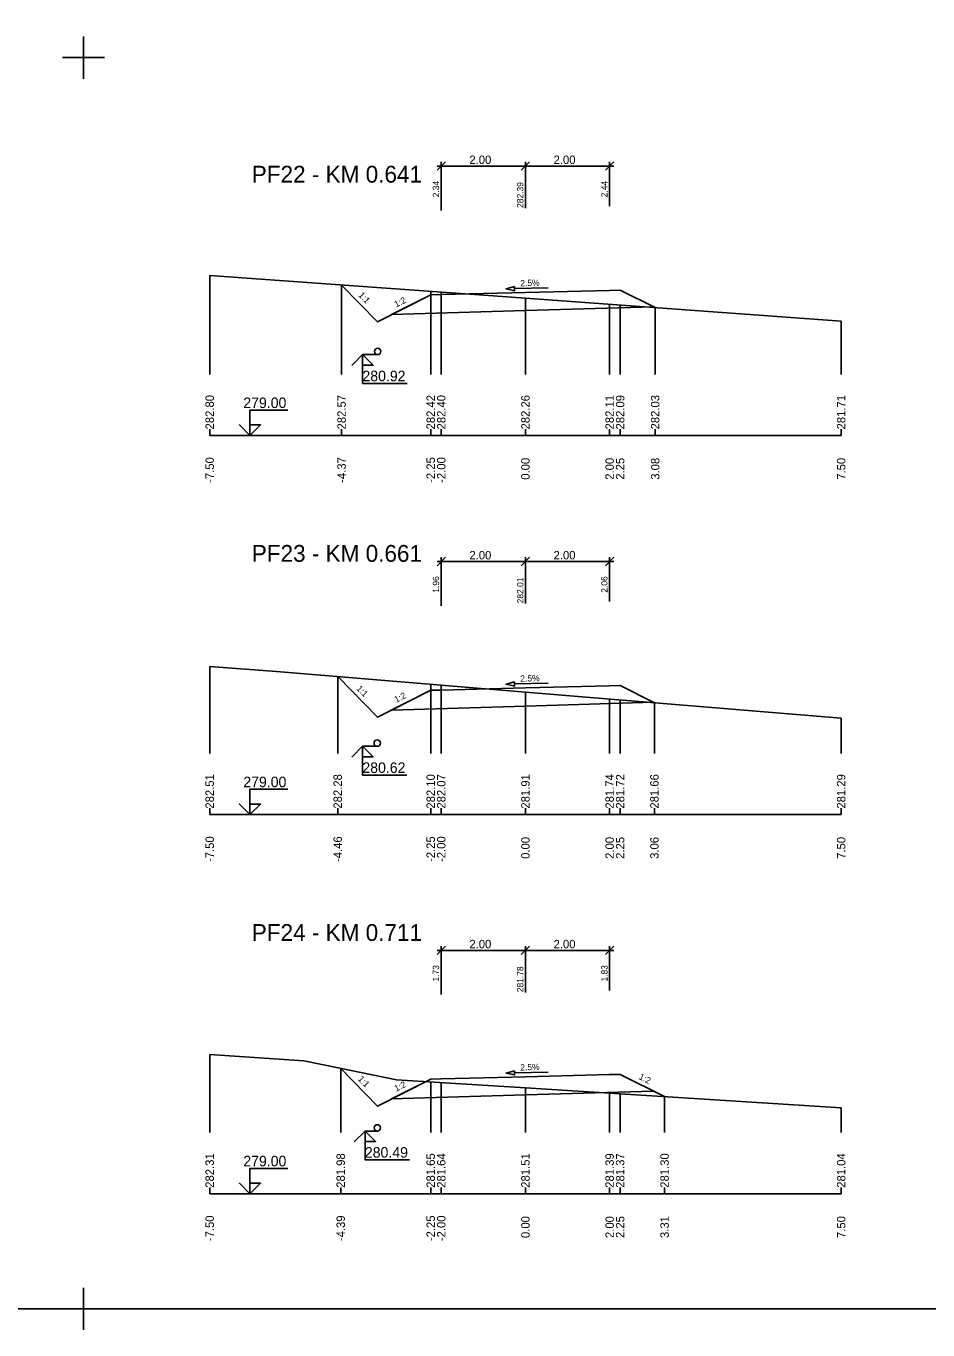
# Model space of a CAD drawing. Extents: x -5 to 1895, y -2 to 602.
# Drawn here: x 1456.4 to 1670.6, y -2.3 to 307.2 of the extents above; entities that cross this region are included whole.
import ezdxf

# ---------------------------------------------------------------- set-up
doc = ezdxf.new("R2010")
doc.units = 0
for name, color, linetype in [('KOTA', 7, 'Continuous'), ('KOTA_DELKY', 7, 'Continuous'), ('KOTA_DELKY_CONT', 7, 'Continuous'), ('KRIZENI', 7, 'Continuous'), ('NS_TELESO_VOZOVKY', 7, 'Continuous'), ('NS_V_PF', 7, 'Continuous'), ('REZY_PF_PUVODNI', 7, 'Continuous'), ('SESTAVY_REZU_PF', 7, 'Continuous'), ('SKLON', 7, 'Continuous'), ('SVK', 7, 'Continuous')]:
    doc.layers.add(name, color=color, linetype=linetype)

msp = doc.modelspace()

# ---------------------------------------------------------------- linework, layer by layer
for p, q in [((1470, 304.67), (1470, 294.67)), ((1470, 304.67), (1470, 294.67)), ((1470, 304.67), (1470, 294.67)), ((1470, 304.67), (1470, 294.67)), ((1470, 304.67), (1470, 294.67)), ((1470, 304.67), (1470, 294.67)), ((1470, 304.67), (1470, 294.67)), ((1470, 304.67), (1470, 294.67)), ((1470, 304.67), (1470, 294.67)), ((1470, 304.67), (1470, 294.67)), ((1470, 304.67), (1470, 294.67)), ((1470, 304.67), (1470, 294.67)), ((1470, 304.67), (1470, 294.67)), ((1470, 304.67), (1470, 294.67)), ((1470, 304.67), (1470, 294.67)), ((1470, 304.67), (1470, 294.67)), ((1470, 304.67), (1470, 294.67)), ((1470, 304.67), (1470, 294.67)), ((1470, 304.67), (1470, 294.67)), ((1470, 304.67), (1470, 294.67)), ((1470, 304.67), (1470, 294.67)), ((1470, 304.67), (1470, 294.67)), ((1470, 304.67), (1470, 294.67)), ((1470, 304.67), (1470, 294.67)), ((1470, 304.67), (1470, 294.67)), ((1470, 304.67), (1470, 294.67)), ((1470, 304.67), (1470, 294.67)), ((1470, 304.67), (1470, 294.67)), ((1470, 304.67), (1470, 294.67)), ((1470, 304.67), (1470, 294.67)), ((1470, 304.67), (1470, 294.67)), ((1470, 304.67), (1470, 294.67)), ((1470, 304.67), (1470, 294.67)), ((1470, 304.67), (1470, 294.67)), ((1470, 304.67), (1470, 294.67)), ((1470, 304.67), (1470, 294.67)), ((1470, 304.67), (1470, 294.67)), ((1470, 304.67), (1470, 294.67)), ((1470, 304.67), (1470, 294.67)), ((1470, 304.67), (1470, 294.67)), ((1470, 304.67), (1470, 294.67)), ((1470, 304.67), (1470, 294.67)), ((1470, 304.67), (1470, 294.67)), ((1470, 304.67), (1470, 294.67)), ((1470, 304.67), (1470, 294.67)), ((1470, 304.67), (1470, 294.67)), ((1470, 304.67), (1470, 294.67)), ((1470, 304.67), (1470, 294.67)), ((1470, 304.67), (1470, 294.67)), ((1470, 304.67), (1470, 294.67)), ((1470, 304.67), (1470, 294.67)), ((1470, 304.67), (1470, 294.67)), ((1470, 304.67), (1470, 294.67)), ((1470, 304.67), (1470, 294.67)), ((1475, 299.67), (1465, 299.67)), ((1475, 299.67), (1465, 299.67)), ((1475, 299.67), (1465, 299.67)), ((1475, 299.67), (1465, 299.67)), ((1475, 299.67), (1465, 299.67)), ((1475, 299.67), (1465, 299.67)), ((1475, 299.67), (1465, 299.67)), ((1475, 299.67), (1465, 299.67)), ((1475, 299.67), (1465, 299.67)), ((1475, 299.67), (1465, 299.67)), ((1475, 299.67), (1465, 299.67)), ((1475, 299.67), (1465, 299.67)), ((1475, 299.67), (1465, 299.67)), ((1475, 299.67), (1465, 299.67)), ((1475, 299.67), (1465, 299.67)), ((1475, 299.67), (1465, 299.67)), ((1475, 299.67), (1465, 299.67)), ((1475, 299.67), (1465, 299.67)), ((1475, 299.67), (1465, 299.67)), ((1475, 299.67), (1465, 299.67)), ((1475, 299.67), (1465, 299.67)), ((1475, 299.67), (1465, 299.67)), ((1475, 299.67), (1465, 299.67)), ((1475, 299.67), (1465, 299.67)), ((1475, 299.67), (1465, 299.67)), ((1475, 299.67), (1465, 299.67)), ((1475, 299.67), (1465, 299.67)), ((1475, 299.67), (1465, 299.67)), ((1475, 299.67), (1465, 299.67)), ((1475, 299.67), (1465, 299.67)), ((1475, 299.67), (1465, 299.67)), ((1475, 299.67), (1465, 299.67)), ((1475, 299.67), (1465, 299.67)), ((1475, 299.67), (1465, 299.67)), ((1475, 299.67), (1465, 299.67)), ((1475, 299.67), (1465, 299.67)), ((1475, 299.67), (1465, 299.67)), ((1475, 299.67), (1465, 299.67)), ((1475, 299.67), (1465, 299.67)), ((1475, 299.67), (1465, 299.67)), ((1475, 299.67), (1465, 299.67)), ((1475, 299.67), (1465, 299.67)), ((1475, 299.67), (1465, 299.67)), ((1475, 299.67), (1465, 299.67)), ((1475, 299.67), (1465, 299.67)), ((1475, 299.67), (1465, 299.67)), ((1475, 299.67), (1465, 299.67)), ((1475, 299.67), (1465, 299.67)), ((1475, 299.67), (1465, 299.67)), ((1475, 299.67), (1465, 299.67)), ((1475, 299.67), (1465, 299.67)), ((1475, 299.67), (1465, 299.67)), ((1475, 299.67), (1465, 299.67)), ((1475, 299.67), (1465, 299.67)), ((1470, 7.67), (1470, -2.33)), ((1470, 7.67), (1470, -2.33)), ((1470, 7.67), (1470, -2.33)), ((1470, 7.67), (1470, -2.33)), ((1470, 7.67), (1470, -2.33)), ((1470, 7.67), (1470, -2.33)), ((1470, 7.67), (1470, -2.33)), ((1470, 7.67), (1470, -2.33)), ((1470, 7.67), (1470, -2.33)), ((1470, 7.67), (1470, -2.33)), ((1470, 7.67), (1470, -2.33)), ((1470, 7.67), (1470, -2.33)), ((1475, 2.67), (1465, 2.67)), ((1475, 2.67), (1465, 2.67)), ((1475, 2.67), (1465, 2.67)), ((1475, 2.67), (1465, 2.67)), ((1475, 2.67), (1465, 2.67)), ((1475, 2.67), (1465, 2.67)), ((1475, 2.67), (1465, 2.67)), ((1475, 2.67), (1465, 2.67)), ((1475, 2.67), (1465, 2.67)), ((1475, 2.67), (1465, 2.67)), ((1475, 2.67), (1465, 2.67)), ((1475, 2.67), (1465, 2.67))]:
    msp.add_line(p, q)
msp.add_lwpolyline([(0, 596.67), (1890, 596.67), (1890, 2.67), (0, 2.67)], close=True)
at = {"layer": 'KOTA'}
for points in [[(1536.33, 229.18), (1533.83, 226.68), (1536.33, 229.18), (1536.33, 222.36), (1546.87, 222.36)], [(1539.91, 229.18), (1536.33, 229.18)], [(1536.33, 229.18), (1538.83, 226.68), (1536.33, 226.68), (1536.33, 229.18)], [(1536.33, 229.18), (1538.83, 226.68), (1536.33, 226.68)], [(1509.57, 210), (1507.07, 212.5), (1509.57, 210), (1509.57, 216), (1518.57, 216)], [(1509.57, 210), (1512.07, 212.5), (1509.57, 212.5), (1509.57, 210)], [(1509.57, 210), (1512.07, 212.5), (1509.57, 212.5)], [(1536.32, 136.21), (1533.82, 133.71), (1536.32, 136.21), (1536.32, 129.39), (1546.86, 129.39)], [(1539.79, 136.21), (1536.32, 136.21)], [(1536.32, 136.21), (1538.82, 133.71), (1536.32, 133.71), (1536.32, 136.21)], [(1536.32, 136.21), (1538.82, 133.71), (1536.32, 133.71)], [(1509.57, 120), (1507.07, 122.5), (1509.57, 120), (1509.57, 126), (1518.57, 126)], [(1509.57, 120), (1512.07, 122.5), (1509.57, 122.5), (1509.57, 120)], [(1509.57, 120), (1512.07, 122.5), (1509.57, 122.5)], [(1536.91, 44.88), (1534.41, 42.38), (1536.91, 44.88), (1536.91, 38.06), (1547.46, 38.06)], [(1539.83, 44.88), (1536.91, 44.88)], [(1536.91, 44.88), (1539.41, 42.38), (1536.91, 42.38), (1536.91, 44.88)], [(1536.91, 44.88), (1539.41, 42.38), (1536.91, 42.38)], [(1509.57, 30), (1507.07, 32.5), (1509.57, 30), (1509.57, 36), (1518.57, 36)], [(1509.57, 30), (1512.07, 32.5), (1509.57, 32.5), (1509.57, 30)], [(1509.57, 30), (1512.07, 32.5), (1509.57, 32.5)]]:
    msp.add_lwpolyline(points, dxfattribs=at)
at = {"layer": 'KOTA_DELKY'}
for points in [[(1554, 272.93), (1556, 274.93)], [(1554, 273.93), (1576, 273.93)], [(1555, 263.43), (1555, 274.93)], [(1574, 272.93), (1576, 274.93)], [(1574, 272.93), (1576, 274.93)], [(1574, 273.93), (1596, 273.93)], [(1575, 263.93), (1575, 274.93)], [(1575, 263.93), (1575, 274.93)], [(1594, 272.93), (1596, 274.93)], [(1595, 264.43), (1595, 274.93)], [(1554, 179.07), (1556, 181.07)], [(1554, 180.07), (1576, 180.07)], [(1555, 169.57), (1555, 181.07)], [(1574, 179.07), (1576, 181.07)], [(1574, 179.07), (1576, 181.07)], [(1574, 180.07), (1596, 180.07)], [(1575, 170.07), (1575, 181.07)], [(1575, 170.07), (1575, 181.07)], [(1594, 179.07), (1596, 181.07)], [(1595, 170.57), (1595, 181.07)], [(1554, 86.76), (1556, 88.76)], [(1554, 87.76), (1576, 87.76)], [(1555, 77.26), (1555, 88.76)], [(1574, 86.76), (1576, 88.76)], [(1574, 86.76), (1576, 88.76)], [(1574, 87.76), (1596, 87.76)], [(1575, 77.76), (1575, 88.76)], [(1575, 77.76), (1575, 88.76)], [(1594, 86.76), (1596, 88.76)], [(1595, 78.26), (1595, 88.76)]]:
    msp.add_lwpolyline(points, dxfattribs=at)
at = {"layer": 'KRIZENI'}
for centre in [(1539.91, 229.93), (1539.79, 136.96), (1539.83, 45.63)]:
    msp.add_circle(centre, 0.75, dxfattribs=at)
at = {"layer": 'NS_TELESO_VOZOVKY'}
for points in [[(1575, 243.93), (1595, 244.43), (1597.5, 244.49), (1605.82, 240.33), (1605.4, 240.54), (1575, 239.63), (1543.2, 238.67), (1552.5, 243.36), (1555, 243.43), (1575, 243.93)], [(1575, 150.07), (1595, 150.57), (1597.5, 150.63), (1605.64, 146.56), (1605.4, 146.68), (1575, 145.77), (1543.2, 144.81), (1552.5, 149.51), (1555, 149.57), (1575, 150.07)], [(1575, 57.76), (1595, 58.26), (1597.5, 58.32), (1608.05, 53.04), (1605.4, 54.37), (1575, 53.46), (1543.2, 52.5), (1552.5, 57.2), (1555, 57.26), (1575, 57.76)]]:
    msp.add_lwpolyline(points, dxfattribs=at)
at = {"layer": 'NS_V_PF'}
for points in [[(1531.33, 245.7), (1539.87, 236.99), (1552.5, 243.36), (1555, 243.43), (1575, 243.93), (1595, 244.43), (1597.5, 244.49), (1605.82, 240.33)], [(1530.41, 152.78), (1539.87, 143.13), (1552.5, 149.51), (1555, 149.57), (1575, 150.07), (1595, 150.57), (1597.5, 150.63), (1605.64, 146.56)], [(1531.12, 59.75), (1539.87, 50.82), (1552.5, 57.2), (1555, 57.26), (1575, 57.76), (1595, 58.26), (1597.5, 58.32), (1608.05, 53.04)]]:
    msp.add_lwpolyline(points, dxfattribs=at)
at = {"layer": 'REZY_PF_PUVODNI'}
for points in [[(1500, 247.96), (1575, 242.55), (1650, 237.15)], [(1500, 155.12), (1515.89, 153.98), (1575, 149.09), (1650, 142.89)], [(1500, 63.07), (1522.34, 61.55), (1527.46, 60.5), (1544.38, 57.03), (1575, 55.11), (1650, 50.42)]]:
    msp.add_lwpolyline(points, dxfattribs=at)
at = {"layer": 'SESTAVY_REZU_PF'}
for points in [[(1500, 210), (1650, 210)], [(1500, 120), (1650, 120)], [(1500, 30), (1650, 30)]]:
    msp.add_lwpolyline(points, dxfattribs=at)
at = {"layer": 'SKLON'}
for points in [[(1572.39, 245.36), (1570.4, 244.81), (1572.41, 244.36), (1572.39, 245.36)], [(1572.4, 244.86), (1580.4, 245.06)], [(1572.39, 151.5), (1570.4, 150.95), (1572.41, 150.5), (1572.39, 151.5)], [(1572.4, 151), (1580.4, 151.2)], [(1572.39, 59.19), (1570.4, 58.64), (1572.41, 58.19), (1572.39, 59.19)], [(1572.4, 58.69), (1580.4, 58.89)]]:
    msp.add_lwpolyline(points, dxfattribs=at)
for points in [[(1572.39, 245.36), (1570.4, 244.81), (1572.41, 244.36)], [(1572.39, 151.5), (1570.4, 150.95), (1572.41, 150.5)], [(1572.39, 59.19), (1570.4, 58.64), (1572.41, 58.19)]]:
    msp.add_lwpolyline(points, close=True, dxfattribs=at)
at = {"layer": 'SVK'}
for points in [[(1500, 224.5), (1500, 247.96)], [(1531.33, 224.5), (1531.33, 245.7)], [(1552.5, 224.5), (1552.5, 244.17)], [(1555, 224.5), (1555, 243.99)], [(1575, 224.5), (1575, 242.55)], [(1595, 224.5), (1595, 241.11)], [(1597.5, 224.5), (1597.5, 240.93)], [(1605.82, 224.5), (1605.82, 240.33)], [(1650, 224.5), (1650, 237.15)], [(1500, 210), (1500, 211.5)], [(1531.33, 210), (1531.33, 211.5)], [(1552.5, 210), (1552.5, 211.5)], [(1555, 210), (1555, 211.5)], [(1575, 210), (1575, 211.5)], [(1595, 210), (1595, 211.5)], [(1597.5, 210), (1597.5, 211.5)], [(1605.82, 210), (1605.82, 211.5)], [(1650, 210), (1650, 211.5)], [(1500, 134.5), (1500, 155.12)], [(1530.41, 134.5), (1530.41, 152.78)], [(1552.5, 134.5), (1552.5, 150.95)], [(1555, 134.5), (1555, 150.75)], [(1575, 134.5), (1575, 149.09)], [(1595, 134.5), (1595, 147.44)], [(1597.5, 134.5), (1597.5, 147.23)], [(1605.64, 134.5), (1605.64, 146.56)], [(1650, 134.5), (1650, 142.89)], [(1500, 120), (1500, 121.5)], [(1530.41, 120), (1530.41, 121.5)], [(1552.5, 120), (1552.5, 121.5)], [(1555, 120), (1555, 121.5)], [(1575, 120), (1575, 121.5)], [(1595, 120), (1595, 121.5)], [(1597.5, 120), (1597.5, 121.5)], [(1605.64, 120), (1605.64, 121.5)], [(1650, 120), (1650, 121.5)], [(1500, 44.5), (1500, 63.07)], [(1531.12, 44.5), (1531.12, 59.75)], [(1552.5, 44.5), (1552.5, 56.52)], [(1555, 44.5), (1555, 56.36)], [(1575, 44.5), (1575, 55.11)], [(1595, 44.5), (1595, 53.86)], [(1597.5, 44.5), (1597.5, 53.7)], [(1608.05, 44.5), (1608.05, 53.04)], [(1650, 44.5), (1650, 50.42)], [(1500, 30), (1500, 31.5)], [(1531.12, 30), (1531.12, 31.5)], [(1552.5, 30), (1552.5, 31.5)], [(1555, 30), (1555, 31.5)], [(1575, 30), (1575, 31.5)], [(1595, 30), (1595, 31.5)], [(1597.5, 30), (1597.5, 31.5)], [(1608.05, 30), (1608.05, 31.5)], [(1650, 30), (1650, 31.5)]]:
    msp.add_lwpolyline(points, dxfattribs=at)

# ---------------------------------------------------------------- texts
at = {"layer": 'KOTA'}
for s, p in [('280.92', (1536.29, 222.86)), ('279.00', (1507.99, 216.5)), ('280.62', (1536.27, 129.89)), ('279.00', (1507.99, 126.5)), ('280.49', (1536.87, 38.56)), ('279.00', (1507.99, 36.5))]:
    msp.add_text(s, height=2.5, dxfattribs=at).set_placement(p)
at = {"layer": 'KOTA_DELKY'}
for p in [(1561.69, 274.43), (1581.69, 274.43), (1561.69, 180.57), (1581.69, 180.57), (1561.69, 88.26), (1581.69, 88.26)]:
    msp.add_text('2.00', height=2, dxfattribs=at).set_placement(p)
at = {"layer": 'KOTA_DELKY_CONT'}
for s, p in [('2.34', (1554.5, 266.52)), ('282.39', (1574.5, 264)), ('2.44', (1594.5, 266.52)), ('1.96', (1554.5, 172.66)), ('2.06', (1594.5, 172.66)), ('282.01', (1574.5, 170.14)), ('1.73', (1554.5, 80.35)), ('281.78', (1574.5, 77.83)), ('1.83', (1594.5, 80.35))]:
    msp.add_text(s, height=1.5, rotation=90, dxfattribs=at).set_placement(p)
at = {"layer": 'SESTAVY_REZU_PF'}
for s, p in [('PF22 - KM 0.641', (1510, 270)), ('PF23 - KM 0.661', (1510, 180)), ('PF24 - KM 0.711', (1510, 90))]:
    msp.add_text(s, height=4, dxfattribs=at).set_placement(p)
at = {"layer": 'SKLON'}
for s, rotation, p in [('2.5%', 1.4321, (1573.8, 245.4)), ('1:1', 314.4213, (1535.21, 243.17)), ('1:2', 26.7649, (1544.32, 240.36)), ('2.5%', 1.4321, (1573.8, 151.54)), ('1:1', 314.4213, (1534.75, 149.78)), ('1:2', 26.7649, (1544.32, 146.5)), ('2.5%', 1.4321, (1573.8, 59.23)), ('1:1', 314.4213, (1535.1, 57.11)), ('1:2', 26.7649, (1544.32, 54.19)), ('1:2', 333.4349, (1601.81, 57.28))]:
    msp.add_text(s, height=1.5, rotation=rotation, dxfattribs=at).set_placement(p)
at = {"layer": 'SVK'}
for s, p in [(' 282.80', (1501, 210.67)), (' 282.57', (1532.33, 210.67)), (' 282.42', (1553.5, 210.67)), (' 282.40', (1556, 210.67)), (' 282.26', (1576, 210.67)), (' 282.11', (1596, 210.67)), (' 282.09', (1598.5, 210.67)), (' 282.03', (1606.82, 210.67)), (' 281.71', (1651, 210.67)), (' -7.50', (1501, 198)), (' -4.37', (1532.33, 198)), (' -2.25', (1553.5, 198)), (' -2.00', (1556, 198)), ('  0.00', (1576, 198)), ('  2.00', (1596, 198)), ('  2.25', (1598.5, 198)), ('  3.08', (1606.82, 198)), ('  7.50', (1651, 198)), (' 282.51', (1501, 120.67)), (' 282.28', (1531.41, 120.67)), (' 282.10', (1553.5, 120.67)), (' 282.07', (1556, 120.67)), (' 281.91', (1576, 120.67)), (' 281.74', (1596, 120.67)), (' 281.72', (1598.5, 120.67)), (' 281.66', (1606.64, 120.67)), (' 281.29', (1651, 120.67)), (' -7.50', (1501, 108)), (' -4.46', (1531.41, 108)), (' -2.25', (1553.5, 108)), (' -2.00', (1556, 108)), ('  0.00', (1576, 108)), ('  2.00', (1596, 108)), ('  2.25', (1598.5, 108)), ('  3.06', (1606.64, 108)), ('  7.50', (1651, 108)), (' 282.31', (1501, 30.67)), (' 281.98', (1532.12, 30.67)), (' 281.65', (1553.5, 30.67)), (' 281.64', (1556, 30.67)), (' 281.51', (1576, 30.67)), (' 281.39', (1596, 30.67)), (' 281.37', (1598.5, 30.67)), (' 281.30', (1609.05, 30.67)), (' 281.04', (1651, 30.67)), (' -7.50', (1501, 18)), (' -4.39', (1532.12, 18)), (' -2.25', (1553.5, 18)), (' -2.00', (1556, 18)), ('  0.00', (1576, 18)), ('  2.00', (1596, 18)), ('  2.25', (1598.5, 18)), ('  3.31', (1609.05, 18)), ('  7.50', (1651, 18))]:
    msp.add_text(s, height=2, rotation=90, dxfattribs=at).set_placement(p)

doc.saveas('drawing.dxf')
